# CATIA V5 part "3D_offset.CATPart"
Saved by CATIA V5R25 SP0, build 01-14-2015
Part number: Part1
Bounding box of the stored display mesh (mm): x -119.212 to 139.075, y -20 to 0.001, z -1.314 to 92.737
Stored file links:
  E:\cadcim\GSD_cat_v5-6r2014\Part_files\3D_offset.CATPart
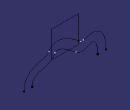
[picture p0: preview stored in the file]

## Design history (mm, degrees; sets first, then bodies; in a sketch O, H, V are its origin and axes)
Set1
  Plane1: type Offset, RefPlane zx-plane, Offset 20, reversed
  Plane2: type Offset, RefPlane Plane1, Offset 20, reversed
  Sketch1 on zx-plane, origin (0, 0, 0), H (-1, 0, 0), V (0, 0, 1)
    spline S1 through (91.2267, 2.5149) (66.4023, 45.9575) (45.4198, 38.8648) (17.3446, 45.9575)
  Sketch2 on Plane1, origin (0, -20, 0), H (-1, 0, 0), V (0, 0, 1)
    spline S1 through (-32.364, 58.2527) (-70.3912, 34.0536) (-101.7704, 22.6188) (-111.0777, -1.3144)
  Connect1: Curve1 Sketch2, Point1 vertex of Sketch2, Tension1 1, Curve2 Sketch1, Point2 vertex of Sketch1, Tension2 1
  Join1: Elements (Connect1; Sketch1; Sketch2)
  3DCurveOffset1: Curve Join1, Direction Plane2, Offset -28, CornerRadius 10, CornerTension 0.5
Body1 (main body)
